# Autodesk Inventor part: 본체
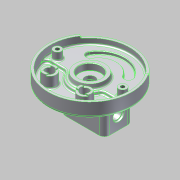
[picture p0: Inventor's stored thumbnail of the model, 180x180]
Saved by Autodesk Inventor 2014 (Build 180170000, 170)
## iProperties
Company: 한국ATC센터
Created: 2015-04
Part Number: 본체
Document SubType Name: Modeling
Designer: KYOUNG IL JANG
Density: 2.71 g/cm^3
Material: 알루미늄 6061
Mass: 1340.83 g
Surface Area: 1387.38 cm^2
Volume: 494.771 cm^3
Appearance: 매끄러움 - 흰색
Author: KYOUNG IL JANG
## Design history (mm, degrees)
sketch "스케치1"
  geometry: L1 (-59, -19)-(-59, 19); L2 (59, 19)-(59, -19); L3 (-41, 19)-(-41, -19); L4 (41, -19)-(41, 19); L5 (38.527, 33.023)-(55.442, 39.179); L6 (-38.527, 33.023)-(-55.442, 39.179); C1 r 90 at (0, 0); C2 r 95 at (0, 0); A1 r 59 centre (0, 19) between (59, 19) and (-59, 19); A2 r 59 centre (0, -19) between (-59, -19) and (59, -19); A3 r 41 centre (0, -19) between (-41, -19) and (41, -19); A4 r 41 centre (0, 19) between (41, 19) and (-41, 19); 2 further points
  constraints: 12 end point, 12 point on circle, 6 centre point, 4 tangent, 2 parallel, 2 point on line, 1 coincident, 1 horizontal alignment, 1 midpoint, 1 vertical, 1 vertical alignment, 3 other
  dimensions: "d2" = 180 diameter of C1; "d3" = 156 dimension on A2 A1; "d4" = 118 distance between parallel lines of L2 L1; "d5" = 18 distance between parallel lines of L2 L4; "d8" = 190 diameter of C2; "d124" = 110 deg dimension on A1.centre point (0, 0) L5.end; "d125" = 140 deg angle of L5 L6
extrude "돌출1" new body sketch "스케치1" distance "d6" = 14; taper "d7" = 0 deg
extrude "돌출2" join sketch "스케치1" distance "d9" = 13; taper "d10" = 0 deg
extrude "돌출3" cut sketch "스케치1" distance "d11" = 7; taper "d12" = 0 deg
sketch "스케치2"
  geometry: C1 r 11.5 at (0, 0); 1 further point
  constraints: 1 centre point, 1 coincident
  dimensions: "d13" = 23 diameter of C1
extrude "돌출4" cut sketch "스케치2" stored distance "d14" = 7; taper "d15" = 0 deg
fillet "모깎기1"
fillet "모깎기2"
sketch "스케치3"
  geometry: L1 (-73.724, 51.622)-(-77.819, 54.49); L2 (73.724, 51.622)-(77.819, 54.49); L3 (0, 0)-(0, -90); A1 r 95 centre (0, 0) between (-77.819, 54.49) and (77.819, 54.49) reference; A2 r 90 centre (0, 0) between (-73.724, 51.622) and (73.724, 51.622) reference; 1 further point
  constraints: 6 end point, 5 point on circle, 1 point on line, 1 vertical, 1 other
  dimensions: "d16" = 250 deg dimension on L2 L1
extrude "돌출5" join sketch "스케치3" distance "d17" = 5; taper "d18" = 0 deg
hole "구멍1" diameter "d21" = 50; stored, may be unused: countersink angle "d25" = 90 deg, drill point angle "d27" = 0 deg; dims "d19" = 10, "d20" = 10, "d22" = 6, "d23" = 4, "d24" = 2, "d26" = 5
fillet "모깎기3" dims "d28" = 0.3
fillet "모깎기5" dims "d30" = 3
sketch "스케치4"
  geometry: C1 r 35 at (0, 0); C2 r 25 at (0, 0); 1 further point
  constraints: 2 centre point, 1 coincident
  dimensions: "d32" = 70 diameter of C1 (derived); "d36" = 10 radial gap between concentric circles of C1 C2
extrude "돌출6" join sketch "스케치4" distance "d33" = 10; taper "d34" = 0 deg
feature "면 기울기2" dims angle "d37" = 10 deg
chamfer "모따기1" distance "d39" = 1; stored, may be unused: second distance "d40" = 2, angle "d41" = 45 deg
fillet "모깎기7" dims "d42" = 5
sketch "스케치5"
  geometry: L1 (-40.249, -12)-(-89.196, -12); L2 (40.249, -12)-(89.196, -12); A1 r 90 centre (0, 0) between (-89.196, -12) and (89.196, -12) reference; A2 r 42 centre (0, 0) between (-40.249, -12) and (40.249, -12); 1 further point
  constraints: 4 end point, 4 point on circle, 1 centre point, 1 collinear, 1 horizontal, 1 point on line
  dimensions: "d43" = 48 radial gap between concentric circles of A1 A2; "d44" = 12 distance from line of point (0, 0) L1
extrude "돌출7" cut sketch "스케치5" stored distance "d45" = 10; taper "d46" = 0 deg
fillet "모깎기8" dims "d47" = 10
chamfer "모따기2" distance "d49" = 1; stored, may be unused: second distance "d50" = 2, angle "d51" = 45 deg
sketch "스케치8"
  geometry: C1 r 9 at (74, 0); C2 r 9 at (-74, 0); A1 r 74 centre (0, 0) between (74, 0) and (-74, 0); 1 further point
  constraints: 3 centre point, 2 horizontal alignment, 2 point on circle, 1 coincident, 1 equal radius
  dimensions: "d64" = 18 diameter of C1; "d65" = 148 diameter of A1
extrude "돌출9" join sketch "스케치8" stored distance "d66" = 5; taper "d67" = 0 deg
sketch "스케치11"
  geometry: C1 r 15 at (40, -52); C2 r 15 at (-40, -52); 1 further point
  constraints: 2 centre point, 1 equal radius, 1 horizontal alignment
  dimensions: "d82" = 52 vertical distance of point (0, 0) C1.centre; "d83" = 30 diameter of C1; "d84" = 80 distance of C2.centre C1.centre; "d85" = 40 horizontal distance of point (0, 0) C1.centre (= 0.5 x d84)
extrude "돌출10" join sketch "스케치11" stored distance "d86" = 10; taper "d87" = 0 deg
node "구멍3"
node "구멍5"
hole "구멍6" diameter "d92" = 20; stored, may be unused: countersink angle "d96" = 90 deg, drill point angle "d98" = 118 deg; dims "d90" = 10, "d91" = 10, "d93" = 6, "d94" = 4, "d95" = 2, "d97" = 8
hole "구멍7" diameter "d101" = 20; stored, may be unused: countersink angle "d105" = 90 deg, drill point angle "d107" = 118 deg; dims "d99" = 10, "d100" = 10, "d102" = 6, "d103" = 4, "d104" = 2, "d106" = 8
fillet "모깎기13" dims "d108" = 3
sketch "스케치13"
  geometry: L1 (-20.252, -58)-(-26, -58); L2 (-42, -58)-(-47.748, -58); L3 (-20.252, -46)-(-26, -46); L4 (-42, -46)-(-47.748, -46); L5 (-108, -65.748)-(-108, -60); L6 (-108, -44)-(-108, -38.252); L7 (-120, -44)-(-120, -38.252); L8 (-120, -60)-(-120, -65.748); A1 r 15 centre (-34, -52) between (-20.252, -58) and (-47.748, -58) reference; A2 r 10 centre (-34, -52) between (-26, -58) and (-42, -58) reference; A3 r 15 centre (-114, -52) between (-108, -65.748) and (-108, -38.252) reference; A4 r 10 centre (-114, -52) between (-108, -60) and (-108, -44) reference; 1 further point
  constraints: 16 end point, 16 point on circle, 3 equal length, 3 point on line, 2 collinear, 1 horizontal, 1 perpendicular
  dimensions: "d114" = 12 distance between parallel lines of L4 L2; "d115" = 6 distance from line of A1.centre L2 (= 0.5 x d114); "d116" = 12 distance between parallel lines of L8 L5 (= d114); "d117" = 6 distance from line of A3.centre L5 (= d115)
extrude "돌출12" join sketch "스케치13" distance "d118" = 3; taper "d119" = 0 deg
fillet "모깎기14" dims "d120" = 1
sketch "스케치14"
  geometry: L1 (23, 32.5)-(-53, 32.5); L2 (-65, 20.5)-(-65, -20.5); L3 (-53, -32.5)-(23, -32.5); L4 (35, -20.5)-(35, 20.5); L5 (30, 20.5)-(30, -20.5); L6 (23, -27.5)-(-53, -27.5); L7 (-60, -20.5)-(-60, 20.5); L8 (-53, 27.5)-(23, 27.5); A1 r 12 centre (-53, -20.5) between (-65, -20.5) and (-53, -32.5); A2 r 12 centre (-53, 20.5) between (-53, 32.5) and (-65, 20.5); A3 r 12 centre (23, 20.5) between (35, 20.5) and (23, 32.5); A4 r 12 centre (23, -20.5) between (23, -32.5) and (35, -20.5); A5 r 7 centre (23, -20.5) between (23, -27.5) and (30, -20.5); A6 r 7 centre (-53, -20.5) between (-60, -20.5) and (-53, -27.5); A7 r 7 centre (-53, 20.5) between (-53, 27.5) and (-60, 20.5); A8 r 7 centre (23, 20.5) between (30, 20.5) and (23, 27.5); A9 r 6 centre (-23, -25) between (-17.546, -27.5) and (-28.454, -27.5); A10 r 6 centre (-23, 25) between (-28.454, 27.5) and (-17.546, 27.5); 6 further points
  constraints: 20 point on circle, 16 end point, 12 point on line, 10 centre point, 8 tangent, 4 equal radius, 4 parallel, 2 perpendicular, 1 horizontal, 1 horizontal alignment, 1 midpoint, 1 vertical alignment, 7 other
  dimensions: "d126" = 35 distance from line of point (0, 0) L4; "d127" = 65 distance of point (35, -32.5) point (35, 32.5); "d128" = 100 distance of point (35, 32.5) point (-65, 32.5); "d132" = 12 radius of A1; "d133" = 5 distance between parallel lines of L5 L4; "d141" = 42 distance from line of A9.centre L2; "d142" = 12 diameter of A9; "d143" = 50 distance of A10.centre A9.centre; "d144" = 25 vertical distance of point (0, 0) A9.centre (= 0.5 x d143)
extrude "돌출13" join sketch "스케치14" distance "d130" = 58; taper "d131" = 0 deg
fillet "모깎기16" dims "d145" = 3
hole "구멍8" diameter "d148" = 4.134; stored, may be unused: countersink angle "d152" = 90 deg, drill point angle "d154" = 118 deg; dims "d146" = 10, "d147" = 10, "d149" = 12, "d150" = 4, "d151" = 2, "d153" = 15
hole "구멍9" diameter "d157" = 4.134; stored, may be unused: countersink angle "d161" = 90 deg, drill point angle "d163" = 118 deg; dims "d155" = 10, "d156" = 10, "d158" = 12, "d159" = 4, "d160" = 2, "d162" = 15
sketch "스케치17"
  geometry: L1 (-58, 110.5)-(-58, -69.5) reference; C1 r 15 at (-29.5, 20.5); 1 further point
  constraints: 1 centre point, 1 horizontal alignment
  dimensions: "d164" = 28.5 distance from line of C1.centre L1; "d165" = 30 diameter of C1
extrude "돌출16" join sketch "스케치17" distance "d166" = 28; taper "d167" = 0 deg
fillet "모깎기17" dims "d168" = 1
hole "구멍10" diameter "d171" = 22; stored, may be unused: countersink angle "d175" = 90 deg, drill point angle "d177" = 118 deg; dims "d169" = 10, "d170" = 10, "d172" = 12, "d173" = 26, "d174" = 4, "d176" = 15
node "솔리드1"
sketch "스케치9"
  geometry: 1 further point
hole "구멍2" sketch "스케치9" diameter "d68" = 8.376; stored, may be unused: countersink angle "d72" = 90 deg, drill point angle "d74" = 120 deg; dims "d69" = 16, "d70" = 4, "d71" = 2, "d73" = 21
sketch "스케치10"
  geometry: 1 further point
hole "구멍4" sketch "스케치10" diameter "d75" = 8.376; stored, may be unused: countersink angle "d79" = 90 deg, drill point angle "d81" = 120 deg; dims "d76" = 16, "d77" = 4, "d78" = 2, "d80" = 21
